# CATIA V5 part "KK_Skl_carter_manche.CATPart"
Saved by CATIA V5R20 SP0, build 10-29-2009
Part number: Skl_carter_manche
Publications: "Droite.4", "Axe_pivot_carter1_carter2.1", "Point.2", "Point.3", "Plan_Ref1", "Plan.Ref6"
Bounding box of the stored display mesh (mm): x -20 to 20, y 0 to 100, z 0 to 0
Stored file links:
  G:\Khaled_CFAO_2011\ST2M\ST2M_GR2\aandujar\Khaled\CAD_thinkMOTION\KK_Skl_carter_manche.CATPart
  G:\Khaled_CFAO_2011\ST2M\ST2M_GR2\aandujar\Khaled\CAD_thinkMOTION\KK_Skl_scie_mecanique.CATProduct
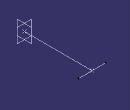
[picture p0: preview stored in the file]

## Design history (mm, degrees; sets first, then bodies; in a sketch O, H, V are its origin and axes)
WSupportSet1: ActiveGrid {3dwsupport RefPoint {point stored without definition}, 3DWOS ({wsupport Support xy-plane, RefPoint {3dwsupport}, GridIn {cartgrid Value 100, Stepbid1 0, Value 100, Stepbid2 0, Direction (1, 0, 0)}, GeometricData ({line type PtDir, Direction (1, 0, 0), Support xy-plane}; {line type PtDir, Direction (0, 1, 0), Support yz-plane})}; {wsupport Support yz-plane, RefPoint {3dwsupport}, GridIn {cartgrid Value 100, Stepbid1 0, Value 100, Stepbid2 0, Direction (0, 1, 0)}, GeometricData ({line type PtDir, Direction (0, 1, 0), Support yz-plane}; {line type PtDir, Direction (0, 0, 1), Support zx-plane})}; {wsupport Support zx-plane, RefPoint {3dwsupport}, GridIn {cartgrid Value 100, Stepbid1 0, Value 100, Stepbid2 0, Direction (0, 0, 1)}, GeometricData ({line type PtDir, Direction (0, 0, 1), Support zx-plane}; {line type PtDir, Direction (1, 0, 0), Support xy-plane})}), GeometricData ({line type PtDir, RefPoint {point stored without definition}, Direction (1, 0, 0), Support xy-plane}; {line type PtDir, RefPoint {point stored without definition}, Direction (0, 1, 0), Support yz-plane}; {line type PtDir, RefPoint {point stored without definition}, Direction (0, 0, 1), Support zx-plane})}
Set1
  Line1: type PtDir, LineFirstUpto Point3, LineSecondUpto Point4, RefPoint Point1, Direction Plane2, Start -20, End 20
  Line2 "Axe_pivot_carter1_carter2.1": type Normal, RefPoint Point1, RefSkin Plane1, Start -20, End 20
Set2
  Point1: linked copy from another document
  Point2: linked copy from another document
  Plane1 "Plan_Ref1": linked copy from another document
  Plane2 "Plan.Ref6": linked copy from another document
  Point3: linked copy from another document
  Point4: linked copy from another document
Body1 (main body)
